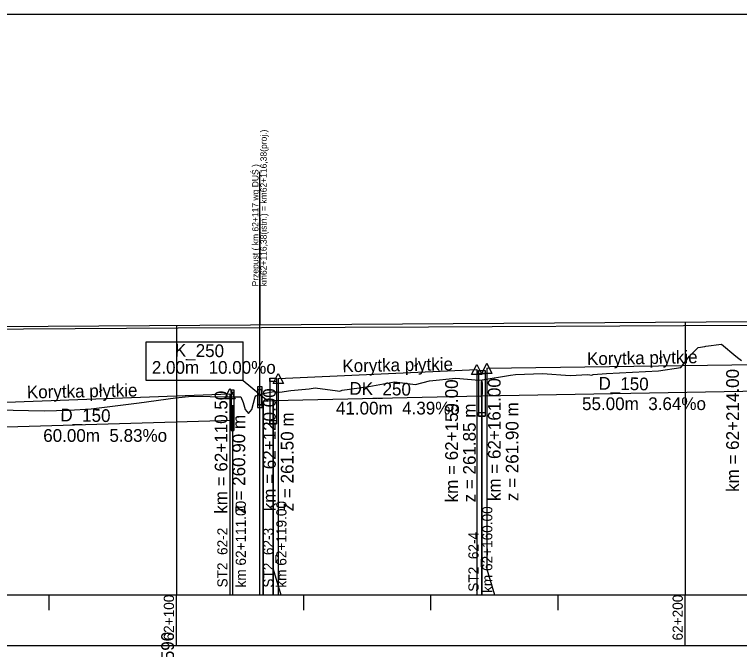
# Model space of a CAD drawing. Extents: x 6445630 to 6518227, y 5499240 to 5511716.
# Drawn here: x 6461299.4 to 6461441.9, y 5508580.5 to 5508705.3 of the extents above; entities that cross this region are included whole.
import ezdxf

# ---------------------------------------------------------------- set-up
doc = ezdxf.new("R2010")
doc.units = 0
for name, color, linetype in [('TOR_PROF-drenaze', 7, 'Continuous'), ('TOR_PROF-drenokolektory', 7, 'Continuous'), ('TOR_PROF-obiekty+opisy', 7, 'Continuous'), ('TOR_PROF-opisy glowne', 7, 'Continuous'), ('TOR_PROF-opisy pomocnicze', 7, 'Continuous'), ('TOR_PROF-rowy otwarte', 7, 'Continuous'), ('TOR_PROF-studnie i osadniki', 7, 'Continuous'), ('TOR_PROF-tabelka-pochylenia proj T1', 7, 'Continuous'), ('TOR_PROF-tor istniejacy T2', 7, 'Continuous'), ('TOR_PROF-tor projektowany', 7, 'Continuous'), ('TOR_PROF-uklad odniesienia', 7, 'Continuous'), ('TOR_PS_ODW-drenaze', 7, 'Continuous'), ('TOR_RAMKI-dodatkowe3', 7, 'Continuous'), ('TOR_RAMKI-MASKA WYCIECIA', 7, 'Continuous')]:
    doc.layers.add(name, color=color, linetype=linetype)

msp = doc.modelspace()

# ---------------------------------------------------------------- linework, layer by layer
at = {"layer": 'TOR_PROF-drenaze'}
for points in [[(6461391.21, 5508630.29), (6461350.21, 5508629.39)], [(6461446.21, 5508631.29), (6461391.21, 5508630.29)], [(6461350.21, 5508629.39), (6461348.21, 5508629.29)], [(6461342.21, 5508625.54), (6461282.21, 5508623.79)]]:
    msp.add_lwpolyline(points, dxfattribs=at)
at = {"layer": 'TOR_PROF-drenokolektory'}
for points in [[(6461391.21, 5508630.29), (6461391.21, 5508596.29), (6461391.21, 5508591.29), (6461391.21, 5508591.29)], [(6461350.21, 5508629.39), (6461350.21, 5508596.29), (6461350.21, 5508591.29), (6461350.21, 5508591.29)], [(6461342.21, 5508625.54), (6461342.21, 5508596.29), (6461342.21, 5508591.29), (6461342.21, 5508591.29)], [(6461342.21, 5508625.54), (6461342.21, 5508596.29), (6461342.21, 5508591.29), (6461342.21, 5508591.29)]]:
    msp.add_lwpolyline(points, dxfattribs=at)
at = {"layer": 'TOR_PROF-obiekty+opisy'}
for p, q in [((6461347.59, 5508591.29), (6461347.59, 5508674.38)), ((6461347.59, 5508665.37), (6461347.59, 5508644.34)), ((6461325.25, 5508641.01), (6461344.33, 5508641.01)), ((6461325.25, 5508633.36), (6461325.25, 5508641.01)), ((6461344.33, 5508633.36), (6461344.33, 5508641.01)), ((6461344.33, 5508633.36), (6461325.25, 5508633.36)), ((6461344.33, 5508633.36), (6461349.21, 5508629.34)), ((6461391.21, 5508591.29), (6461391.21, 5508630.29)), ((6461348.21, 5508591.29), (6461348.21, 5508629.29)), ((6461350.21, 5508591.29), (6461350.21, 5508629.39))]:
    msp.add_line(p, q, dxfattribs=at)
for points in [[(6461348.05, 5508632.17), (6461347.13, 5508632.17), (6461347.13, 5508628.09), (6461348.05, 5508628.09)], [(6461347.97, 5508631.63), (6461347.22, 5508631.63), (6461347.22, 5508628.63), (6461347.97, 5508628.63)]]:
    msp.add_lwpolyline(points, close=True, dxfattribs=at)
for points in [[(6461348.05, 5508628.09), (6461348.05, 5508632.17), (6461347.13, 5508632.17), (6461347.13, 5508628.09), (6461348.05, 5508628.09)], [(6461347.97, 5508628.63), (6461347.22, 5508628.63), (6461347.22, 5508631.63), (6461347.97, 5508631.63), (6461347.97, 5508628.63)]]:
    msp.add_lwpolyline(points, dxfattribs=at)
at = {"layer": 'TOR_PROF-opisy pomocnicze'}
for p, q in [((6461390.21, 5508635.54), (6461390.21, 5508608.54)), ((6461392.21, 5508635.79), (6461392.21, 5508608.79)), ((6461351.21, 5508633.79), (6461351.21, 5508606.79)), ((6461341.71, 5508630.79), (6461341.71, 5508603.79))]:
    msp.add_line(p, q, dxfattribs=at)
for points in [[(6461390.21, 5508636.54), (6461391.21, 5508634.54), (6461389.21, 5508634.54)], [(6461392.21, 5508636.79), (6461393.21, 5508634.79), (6461391.21, 5508634.79)], [(6461351.21, 5508634.79), (6461352.21, 5508632.79), (6461350.21, 5508632.79)], [(6461341.71, 5508631.79), (6461342.71, 5508629.79), (6461340.71, 5508629.79)]]:
    msp.add_lwpolyline(points, close=True, dxfattribs=at)
at = {"layer": 'TOR_PROF-rowy otwarte'}
for p, q in [((6461392.21, 5508635.79), (6461445.21, 5508636.54)), ((6461351.21, 5508633.79), (6461390.21, 5508635.54)), ((6461283.21, 5508628.54), (6461341.71, 5508630.79))]:
    msp.add_line(p, q, dxfattribs=at)
for points in [[(6461390.21, 5508635.54), (6461390.21, 5508596.29), (6461390.21, 5508591.29), (6461390.21, 5508591.29)], [(6461390.21, 5508635.54), (6461390.21, 5508596.29), (6461390.21, 5508591.29), (6461390.21, 5508591.29)], [(6461392.21, 5508635.79), (6461392.21, 5508596.29), (6461393.71, 5508591.29), (6461393.71, 5508591.29)], [(6461392.21, 5508635.79), (6461392.21, 5508596.29), (6461393.71, 5508591.29), (6461393.71, 5508591.29)], [(6461351.21, 5508633.79), (6461351.21, 5508596.29), (6461351.21, 5508591.29), (6461351.21, 5508591.29)], [(6461351.21, 5508633.79), (6461351.21, 5508596.29), (6461351.21, 5508591.29), (6461351.21, 5508591.29)], [(6461341.71, 5508630.79), (6461341.71, 5508596.29), (6461341.71, 5508591.29), (6461341.71, 5508591.29)], [(6461341.71, 5508630.79), (6461341.71, 5508596.29), (6461341.71, 5508591.29), (6461341.71, 5508591.29)], [(6461391.21, 5508630.29), (6461391.21, 5508596.29), (6461391.21, 5508591.29), (6461391.21, 5508591.29)], [(6461348.21, 5508629.29), (6461348.21, 5508596.29), (6461348.21, 5508591.29), (6461348.21, 5508591.29)], [(6461350.21, 5508629.39), (6461350.21, 5508596.29), (6461351.71, 5508591.29), (6461351.71, 5508591.29)], [(6461342.21, 5508625.54), (6461342.21, 5508596.29), (6461342.21, 5508591.29), (6461342.21, 5508591.29)]]:
    msp.add_lwpolyline(points, dxfattribs=at)
at = {"layer": 'TOR_PROF-studnie i osadniki'}
for p, q in [((6461390.56, 5508635.38), (6461390.56, 5508626.38)), ((6461390.56, 5508635.38), (6461391.86, 5508635.38)), ((6461391.86, 5508635.38), (6461391.86, 5508626.38)), ((6461349.56, 5508633.86), (6461349.56, 5508624.86)), ((6461349.56, 5508633.86), (6461350.86, 5508633.86)), ((6461350.86, 5508633.86), (6461350.86, 5508624.86)), ((6461341.96, 5508631.54), (6461341.96, 5508623.54)), ((6461341.96, 5508631.54), (6461342.46, 5508631.54)), ((6461342.46, 5508631.54), (6461342.46, 5508623.54)), ((6461390.56, 5508626.38), (6461391.86, 5508626.38)), ((6461349.56, 5508624.86), (6461350.86, 5508624.86)), ((6461341.96, 5508623.54), (6461342.46, 5508623.54))]:
    msp.add_line(p, q, dxfattribs=at)
for points in [[(6461390.56, 5508635.38), (6461391.86, 5508635.38), (6461391.86, 5508634.68), (6461390.56, 5508634.68)], [(6461349.56, 5508633.86), (6461350.86, 5508633.86), (6461350.86, 5508633.16), (6461349.56, 5508633.16)], [(6461341.96, 5508631.54), (6461342.46, 5508631.54), (6461342.46, 5508631.04), (6461341.96, 5508631.04)], [(6461390.56, 5508627.08), (6461391.86, 5508627.08), (6461391.86, 5508626.38), (6461390.56, 5508626.38)], [(6461349.56, 5508625.56), (6461350.86, 5508625.56), (6461350.86, 5508624.86), (6461349.56, 5508624.86)], [(6461341.96, 5508624.04), (6461342.46, 5508624.04), (6461342.46, 5508623.54), (6461341.96, 5508623.54)]]:
    msp.add_lwpolyline(points, close=True, dxfattribs=at)
at = {"layer": 'TOR_PROF-tabelka-pochylenia proj T1'}
msp.add_lwpolyline([(6452331.21, 5508571.29), (6462731.21, 5508571.29), (6462731.21, 5508581.29), (6452331.21, 5508581.29)], close=True, dxfattribs=at)
at = {"layer": 'TOR_PROF-tor istniejacy T2'}
msp.add_lwpolyline([(6461480.33, 5508644.34), (6461430.88, 5508644.14), (6461380.73, 5508643.89), (6461331.54, 5508643.64), (6461280.86, 5508643.34), (6461229.91, 5508643.04), (6461180.28, 5508642.79), (6461130.45, 5508642.54), (6461080.72, 5508642.24), (6461030.67, 5508641.99), (6460980.62, 5508641.74), (6460928.07, 5508641.44), (6460879.61, 5508641.04), (6460836.6, 5508640.89), (6460803.37, 5508640.79)], dxfattribs=at)
at = {"layer": 'TOR_PROF-tor projektowany'}
msp.add_line((6460751.21, 5508640.59), (6462357.21, 5508650.69), dxfattribs=at)
msp.add_line((6460751.21, 5508640.59), (6462357.21, 5508650.69), dxfattribs=at)
for points in [[(6461431.21, 5508644.87), (6461431.21, 5508596.29), (6461431.21, 5508591.29), (6461431.21, 5508591.29)], [(6461431.21, 5508644.87), (6461431.21, 5508596.29), (6461431.21, 5508591.29), (6461431.21, 5508591.29)], [(6461331.21, 5508644.24), (6461331.21, 5508596.29), (6461331.21, 5508591.29), (6461331.21, 5508591.29)], [(6461331.21, 5508644.24), (6461331.21, 5508596.29), (6461331.21, 5508591.29), (6461331.21, 5508591.29)], [(6461331.21, 5508644.24), (6461331.21, 5508596.29), (6461331.21, 5508591.29), (6461331.21, 5508591.29)]]:
    msp.add_lwpolyline(points, dxfattribs=at)
at = {"layer": 'TOR_PROF-uklad odniesienia'}
for p, q in [((6452331.21, 5508591.29), (6462731.21, 5508591.29)), ((6452331.21, 5508591.29), (6462731.21, 5508591.29)), ((6461306.21, 5508588.29), (6461306.21, 5508591.29)), ((6461306.21, 5508588.29), (6461306.21, 5508591.29)), ((6461331.21, 5508581.29), (6461331.21, 5508591.29)), ((6461331.21, 5508581.29), (6461331.21, 5508591.29)), ((6461356.21, 5508588.29), (6461356.21, 5508591.29)), ((6461356.21, 5508588.29), (6461356.21, 5508591.29)), ((6461381.21, 5508588.29), (6461381.21, 5508591.29)), ((6461381.21, 5508588.29), (6461381.21, 5508591.29)), ((6461406.21, 5508588.29), (6461406.21, 5508591.29)), ((6461406.21, 5508588.29), (6461406.21, 5508591.29)), ((6461431.21, 5508581.29), (6461431.21, 5508591.29)), ((6461431.21, 5508581.29), (6461431.21, 5508591.29))]:
    msp.add_line(p, q, dxfattribs=at)
at = {"layer": 'TOR_PS_ODW-drenaze'}
for p, q in [((6461391.21, 5508630.29), (6461391.21, 5508609.41)), ((6461342.21, 5508625.54), (6461342.21, 5508604.66))]:
    msp.add_line(p, q, dxfattribs=at)
for centre, major_axis in [((6461391.21, 5508631.79), (0, 1.5)), ((6461391.21, 5508630.29), (0, -0.6)), ((6461342.21, 5508627.04), (0, 1.5)), ((6461342.21, 5508625.54), (0, -0.6))]:
    msp.add_ellipse(centre, major_axis=major_axis, ratio=0.05, dxfattribs=at)
at = {"layer": 'TOR_RAMKI-dodatkowe3'}
for p, q in [((6461435.25, 5508640.12), (6461438.29, 5508640.54)), ((6461438.29, 5508640.54), (6461441.16, 5508638.17)), ((6461432.04, 5508638.15), (6461433.72, 5508639.85)), ((6461433.72, 5508639.85), (6461435.06, 5508640.09)), ((6461435.06, 5508640.09), (6461435.25, 5508640.12)), ((6461430.32, 5508635.92), (6461432.04, 5508638.15)), ((6461441.16, 5508638.17), (6461441.71, 5508637.68)), ((6461441.71, 5508637.68), (6461442.23, 5508637.31)), ((6461425.95, 5508635.26), (6461430.32, 5508635.92)), ((6461391.31, 5508633.55), (6461396.88, 5508634.43)), ((6461396.88, 5508634.43), (6461397.82, 5508634.55)), ((6461397.82, 5508634.55), (6461403.13, 5508634.77)), ((6461403.13, 5508634.77), (6461408.61, 5508634.4)), ((6461408.61, 5508634.4), (6461412.08, 5508634.54)), ((6461412.08, 5508634.54), (6461412.81, 5508634.44)), ((6461412.81, 5508634.44), (6461413.13, 5508634.58)), ((6461413.13, 5508634.58), (6461415.7, 5508634.75)), ((6461415.7, 5508634.75), (6461425.95, 5508635.26)), ((6461369, 5508632.21), (6461374.07, 5508633.11)), ((6461374.07, 5508633.11), (6461378.21, 5508632.62)), ((6461378.21, 5508632.62), (6461380.92, 5508633.34)), ((6461380.92, 5508633.34), (6461386.09, 5508633.84)), ((6461386.09, 5508633.84), (6461390.67, 5508633.44)), ((6461390.67, 5508633.44), (6461391.31, 5508633.55)), ((6461353.68, 5508631.4), (6461357.3, 5508631.77)), ((6461357.3, 5508631.77), (6461358.47, 5508631.93)), ((6461358.47, 5508631.93), (6461362.87, 5508631.36)), ((6461363.76, 5508631.49), (6461369, 5508632.21)), ((6461331.03, 5508629.99), (6461334.23, 5508630.29)), ((6461334.23, 5508630.29), (6461337.82, 5508630.23)), ((6461337.82, 5508630.23), (6461341.06, 5508630.17)), ((6461341.06, 5508630.17), (6461343.83, 5508630.19)), ((6461343.83, 5508630.19), (6461344.34, 5508629.07)), ((6461346.02, 5508627.69), (6461346.68, 5508630.2)), ((6461346.68, 5508630.2), (6461346.8, 5508630.35)), ((6461346.8, 5508630.35), (6461348.29, 5508630.85)), ((6461348.29, 5508630.85), (6461350.34, 5508631.24)), ((6461350.34, 5508631.24), (6461351.54, 5508631.12)), ((6461351.54, 5508631.12), (6461353.68, 5508631.4)), ((6461362.87, 5508631.36), (6461363.32, 5508631.29)), ((6461363.32, 5508631.29), (6461363.76, 5508631.49)), ((6461314.45, 5508627.79), (6461323.84, 5508629.03)), ((6461323.84, 5508629.03), (6461331.03, 5508629.99)), ((6461344.34, 5508629.07), (6461344.72, 5508627.69)), ((6461280.66, 5508627.93), (6461305.17, 5508627.44)), ((6461305.17, 5508627.44), (6461310.03, 5508627.56)), ((6461310.03, 5508627.56), (6461314.45, 5508627.79)), ((6461344.72, 5508627.69), (6461345.37, 5508626.9)), ((6461345.38, 5508626.9), (6461346.02, 5508627.69)), ((6461345.37, 5508626.9), (6461345.38, 5508626.9))]:
    msp.add_line(p, q, dxfattribs=at)
at = {"layer": 'TOR_RAMKI-MASKA WYCIECIA'}
msp.add_lwpolyline([(6460741.75, 5508418.29), (6462761.75, 5508418.29), (6462761.75, 5508705.29), (6460741.75, 5508705.29)], close=True, dxfattribs=at)

# ---------------------------------------------------------------- texts
at = {"layer": 'TOR_PROF-drenaze'}
for s, rotation, p in [('K_250  ', 359.0503, (6461330.87, 5508638.11)), (' 2.00m  10.00%o  ', 0.0409, (6461325.44, 5508634.7)), ('DK_250  ', 359.0503, (6461365.18, 5508630.6)), ('D_150  ', 359.0503, (6461414.14, 5508631.6)), (' 41.00m  4.39%o  ', 0.0409, (6461361.62, 5508626.7)), (' 55.00m  3.64%o  ', 0.0409, (6461409.99, 5508627.57)), ('D_150  ', 359.0503, (6461308.37, 5508625.38)), (' 60.00m  5.83%o  ', 0.0409, (6461304.09, 5508621.33))]:
    msp.add_text(s, height=2.5, rotation=rotation, dxfattribs=at).set_placement(p)
at = {"layer": 'TOR_PROF-obiekty+opisy'}
for s, p in [(' km62+116,38(istn.) = km62+116,38(proj.) ', (6461348.94, 5508651.41)), (' Przepust ( km 62+117 wg DUŚ )', (6461347.32, 5508651.41))]:
    msp.add_text(s, height=1.25, rotation=90, dxfattribs=at).set_placement(p)
at = {"layer": 'TOR_PROF-opisy glowne'}
for s, p in [('km 62+111.00', (6461344.85, 5508592.72)), ('km 62+119.00', (6461352.82, 5508592.69)), ('km 62+160.00', (6461393.28, 5508591.65)), ('ST2_62-2', (6461341.23, 5508592.72)), ('ST2_62-3', (6461350.24, 5508592.69)), ('ST2_62-4', (6461390.58, 5508591.89))]:
    msp.add_text(s, height=2, rotation=90, dxfattribs=at).set_placement(p)
at = {"layer": 'TOR_PROF-opisy pomocnicze'}
for s, rotation, p in [('Korytka płytkie', 1.0438, (6461411.91, 5508636.4)), ('Korytka płytkie', 1.0438, (6461363.83, 5508635)), ('km = 62+214.00', 90, (6461441.75, 5508611.49)), ('km = 62+159.00', 90, (6461386.52, 5508609.44)), ('km = 62+161.00', 90, (6461394.91, 5508609.69)), ('Korytka płytkie', 1.0438, (6461301.82, 5508629.86)), ('km = 62+120.00', 90, (6461350.71, 5508607.69)), ('km = 62+110.50', 90, (6461341.21, 5508607.21)), ('z = 261.90 m', 90, (6461398.41, 5508609.69)), ('z = 261.85 m', 90, (6461390.02, 5508609.44)), ('z = 260.90 m', 90, (6461344.71, 5508607.21)), ('z = 261.50 m', 90, (6461354.21, 5508607.69))]:
    msp.add_text(s, height=2.5, rotation=rotation, dxfattribs=at).set_placement(p)
at = {"layer": 'TOR_PROF-tabelka-pochylenia proj T1'}
msp.add_text('263.590', height=2.5, rotation=90, dxfattribs=at).set_placement((6461330.71, 5508571.93))
at = {"layer": 'TOR_PROF-uklad odniesienia'}
for s, p in [('62+100', (6461330.71, 5508582.31)), ('62+100', (6461330.71, 5508582.31)), ('62+200', (6461430.71, 5508582.31)), ('62+200', (6461430.71, 5508582.31))]:
    msp.add_text(s, height=2, rotation=90, dxfattribs=at).set_placement(p)

doc.saveas('drawing.dxf')
